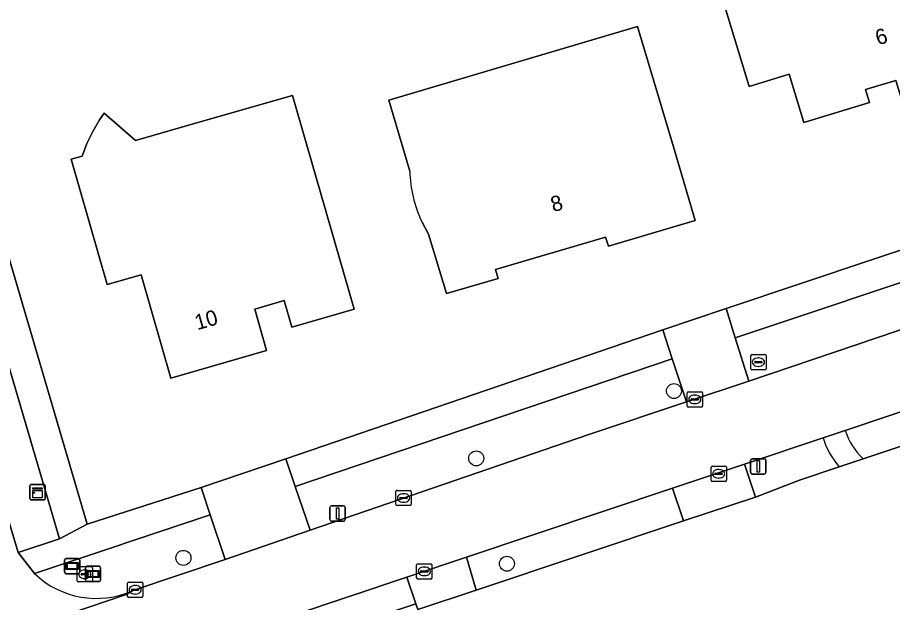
# Model space of a CAD drawing. Extents: x 162417 to 163722, y 384268 to 385417.
# Drawn here: x 163329 to 163386, y 384597 to 384635.2 of the extents above; entities that cross this region are included whole.
import ezdxf

# ---------------------------------------------------------------- set-up
doc = ezdxf.new("R2010")
doc.units = 0
for name, color, linetype in [('IMGEO_Berm_groen', 7, 'Continuous'), ('IMGEO_Boom', 7, 'Continuous'), ('IMGEO_Brandkraan', 7, 'Continuous'), ('IMGEO_Erf', 7, 'Continuous'), ('IMGEO_Groenvoorziening', 7, 'Continuous'), ('IMGEO_Kast', 7, 'Continuous'), ('IMGEO_Kolk', 7, 'Continuous'), ('IMGEO_Lichtmast', 7, 'Continuous'), ('IMGEO_Pand', 7, 'Continuous'), ('IMGEO_Pand_nummerreeks', 7, 'Continuous'), ('IMGEO_Rijbaan_lokaal_open', 7, 'Continuous'), ('IMGEO_Straatnaambord', 7, 'Continuous'), ('IMGEO_Verklikker', 7, 'Continuous'), ('IMGEO_Voetpad_open', 7, 'Continuous')]:
    doc.layers.add(name, color=color, linetype=linetype)

msp = doc.modelspace()

# ---------------------------------------------------------------- linework, layer by layer
at = {"layer": 'IMGEO_Berm_groen'}
for points in [[(163325.769, 384621.2), (163325.485, 384622.16), (163324.587, 384625.199), (163321.795, 384624.338), (163322.7, 384621.313), (163322.986, 384620.355), (163329.005, 384600.235), (163331.704, 384601.119)], [(163390.546, 384616.112), (163391.36, 384616.408), (163390.37, 384619.126), (163375.772, 384614.24), (163376.658, 384611.416)], [(163366.232, 384607.936), (163372.594, 384610.058), (163371.669, 384612.881), (163347.078, 384604.539), (163348.039, 384601.682)]]:
    msp.add_lwpolyline(points, close=True, dxfattribs=at)
for points in [[(163341.529, 384602.689), (163330.054, 384598.864)], [(163336.48, 384597.749), (163342.508, 384599.781), (163341.529, 384602.689)]]:
    msp.add_lwpolyline(points, dxfattribs=at)
msp.add_arc((163334.088, 384603.04), 5.807, 225.9892, 294.3236, dxfattribs=at)
at = {"layer": 'IMGEO_Boom'}
for centre in [(163371.785, 384610.77), (163358.881, 384606.376), (163339.782, 384599.881), (163360.886, 384599.501)]:
    msp.add_circle(centre, 0.489, dxfattribs=at)
at = {"layer": 'IMGEO_Brandkraan'}
for p, q in [((163376.793, 384612.228), (163376.793, 384613.08)), ((163376.868, 384613.154), (163377.72, 384613.154)), ((163377.794, 384613.08), (163377.794, 384612.228)), ((163377.052, 384612.648), (163377.052, 384612.66)), ((163377.49, 384612.611), (163377.092, 384612.611)), ((163377.095, 384612.697), (163377.493, 384612.697)), ((163377.281, 384612.934), (163377.306, 384612.934)), ((163377.536, 384612.66), (163377.536, 384612.648)), ((163377.72, 384612.154), (163376.868, 384612.154)), ((163377.304, 384612.374), (163377.279, 384612.374)), ((163332.846, 384598.385), (163332.846, 384599.237)), ((163332.921, 384599.311), (163333.773, 384599.311)), ((163333.105, 384598.805), (163333.105, 384598.817)), ((163333.543, 384598.768), (163333.145, 384598.768)), ((163333.148, 384598.854), (163333.546, 384598.854)), ((163333.334, 384599.091), (163333.359, 384599.091)), ((163333.589, 384598.817), (163333.589, 384598.805)), ((163333.847, 384599.237), (163333.847, 384598.385)), ((163333.773, 384598.311), (163332.921, 384598.311)), ((163333.357, 384598.531), (163333.332, 384598.531))]:
    msp.add_line(p, q, dxfattribs=at)
for points in [[(163376.793, 384612.228), (163376.793, 384613.08)], [(163376.868, 384613.154), (163377.72, 384613.154)], [(163377.794, 384613.08), (163377.794, 384612.228)], [(163377.72, 384612.154), (163376.868, 384612.154)], [(163332.846, 384598.385), (163332.846, 384599.237)], [(163332.921, 384599.311), (163333.773, 384599.311)], [(163333.847, 384599.237), (163333.847, 384598.385)], [(163333.773, 384598.311), (163332.921, 384598.311)]]:
    msp.add_lwpolyline(points, dxfattribs=at)
for centre, radius, start, end in [((163376.87, 384613.078), 0.0765, 91.552, 178.448), ((163376.87, 384613.078), 0.0765, 91.552, 178.448), ((163377.718, 384613.078), 0.0765, 1.552, 88.448), ((163377.718, 384613.078), 0.0765, 1.552, 88.448), ((163377.092, 384612.657), 0.0403, 85.8775, 175.7526), ((163377.089, 384612.647), 0.0366, 178.938, 274.7102), ((163377.493, 384612.654), 0.043, 264.8664, 352.4533), ((163377.497, 384612.659), 0.0386, 1.7309, 96.639), ((163376.87, 384612.23), 0.0765, 181.552, 268.448), ((163376.87, 384612.23), 0.0765, 181.552, 268.448), ((163377.718, 384612.23), 0.0765, 271.552, 358.448), ((163377.718, 384612.23), 0.0765, 271.552, 358.448), ((163332.923, 384599.235), 0.0765, 91.552, 178.448), ((163332.923, 384599.235), 0.0765, 91.552, 178.448), ((163333.145, 384598.814), 0.0403, 85.8775, 175.7526), ((163333.142, 384598.804), 0.0366, 178.938, 274.7102), ((163333.546, 384598.811), 0.043, 264.8664, 352.4533), ((163333.55, 384598.816), 0.0386, 1.7309, 96.639), ((163333.771, 384599.235), 0.0765, 1.552, 88.448), ((163333.771, 384599.235), 0.0765, 1.552, 88.448), ((163332.923, 384598.387), 0.0765, 181.552, 268.448), ((163332.923, 384598.387), 0.0765, 181.552, 268.448), ((163333.771, 384598.387), 0.0765, 271.552, 358.448), ((163333.771, 384598.387), 0.0765, 271.552, 358.448)]:
    msp.add_arc(centre, radius, start, end, dxfattribs=at)
for centre, major_axis, ratio, start_param, end_param in [((163377.28, 384612.654), (-0.387, 0.002), 0.722429, 4.712389, 7.853982), ((163377.305, 384612.654), (-0.39, 0.002), 0.717154, 1.570796, 4.712389), ((163333.333, 384598.811), (-0.387, 0.002), 0.722429, 4.712389, 7.853982), ((163333.358, 384598.811), (-0.39, 0.002), 0.717154, 1.570796, 4.712389)]:
    msp.add_ellipse(centre, major_axis=major_axis, ratio=ratio, start_param=start_param, end_param=end_param, dxfattribs=at)
at = {"layer": 'IMGEO_Erf'}
for points in [[(163310.09, 384681.76), (163333.508, 384602.071), (163340.928, 384604.472), (163346.471, 384606.34), (163371.048, 384614.758), (163375.186, 384616.159), (163389.679, 384621.017), (163394.532, 384622.596), (163398.708, 384624.299), (163402.801, 384626.194), (163403.314, 384626.415), (163406.716, 384627.995)], [(163354.543, 384625.127), (163353.186, 384629.758), (163369.415, 384634.561), (163371.747, 384626.703)], [(163371.747, 384626.703), (163373.169, 384621.909), (163367.504, 384620.235), (163367.319, 384620.817), (163360.137, 384618.695), (163360.316, 384618.12), (163356.948, 384617.133), (163355.771, 384621.007), (163355.324, 384621.829)], [(163419.582, 384621.874), (163409.408, 384616.22), (163410.03, 384614.861), (163400.639, 384612.147), (163394.917, 384609.966), (163384.126, 384606.347), (163382.571, 384605.826), (163379.98, 384604.957), (163377.103, 384603.845), (163372.405, 384602.287), (163358.873, 384597.777), (163355.069, 384596.509), (163354.943, 384596.875), (163344.075, 384593.215), (163344.183, 384592.925), (163342.307, 384592.282)]]:
    msp.add_lwpolyline(points, dxfattribs=at)
for points in [[(163392.516, 384640.667), (163393.965, 384635.882), (163391.345, 384635.089), (163393.445, 384628.155), (163387.663, 384626.41), (163386.518, 384630.192), (163386.261, 384631.043), (163384.28, 384630.444), (163384.538, 384629.593), (163380.261, 384628.298), (163379.31, 384631.443), (163376.692, 384630.651), (163375.243, 384635.437), (163374.953, 384636.394), (163377.573, 384637.187), (163376.623, 384640.332), (163382.891, 384642.229), (163381.746, 384646.012), (163380.405, 384650.271), (163388.837, 384652.823)], [(163350.916, 384616.107), (163346.854, 384614.936), (163346.352, 384616.675), (163344.429, 384616.12), (163345.208, 384613.419), (163338.963, 384611.616), (163337.021, 384618.356), (163334.807, 384617.718), (163332.449, 384625.902), (163333.165, 384626.108), (163333.478, 384626.928), (163333.86, 384627.718), (163334.308, 384628.472), (163334.611, 384628.896), (163336.658, 384627.116), (163341.022, 384628.374), (163346.891, 384630.066)]]:
    msp.add_lwpolyline(points, close=True, dxfattribs=at)
msp.add_arc((163362.771, 384625.334), 8.231, 181.4417, 205.2039, dxfattribs=at)
at = {"layer": 'IMGEO_Groenvoorziening'}
for points in [[(163384.126, 384606.347), (163394.917, 384609.966), (163395.176, 384610.568), (163394.546, 384612.095), (163382.96, 384608.203)], [(163381.515, 384607.717), (163376.389, 384605.995), (163377.103, 384603.845), (163379.98, 384604.957), (163382.571, 384605.826)]]:
    msp.add_lwpolyline(points, dxfattribs=at)
msp.add_lwpolyline([(163372.405, 384602.287), (163371.696, 384604.423), (163358.243, 384599.918), (163358.873, 384597.777)], close=True, dxfattribs=at)
for centre, radius, start, end in [((163387.063, 384609.486), 4.299, 197.3688, 226.908), ((163386.25, 384609.121), 4.939, 196.5137, 221.8473)]:
    msp.add_arc(centre, radius, start, end, dxfattribs=at)
at = {"layer": 'IMGEO_Kast'}
for p, q in [((163329.764, 384603.741), (163329.764, 384604.582)), ((163329.764, 384604.582), (163329.764, 384603.741)), ((163329.839, 384604.666), (163330.68, 384604.666)), ((163330.68, 384604.666), (163329.839, 384604.666)), ((163330.764, 384604.591), (163330.764, 384603.75)), ((163330.764, 384603.75), (163330.764, 384604.591)), ((163330.689, 384603.666), (163329.848, 384603.666)), ((163329.848, 384603.666), (163330.689, 384603.666))]:
    msp.add_line(p, q, dxfattribs=at)
for points in [[(163329.959, 384604.456), (163330.559, 384604.456), (163330.559, 384604.371), (163329.959, 384604.371), (163329.959, 384604.456)], [(163329.959, 384604.281), (163330.559, 384604.281), (163330.559, 384603.792), (163329.959, 384603.792), (163329.959, 384604.281)]]:
    msp.add_lwpolyline(points, dxfattribs=at)
msp.add_circle((163330.043, 384604.13), 0.0377, dxfattribs=at)
for centre, start, end in [((163329.842, 384604.588), 92.4484, 184.2845), ((163329.842, 384604.588), 92.4484, 184.2845), ((163330.686, 384604.588), 2.4484, 94.2845), ((163330.686, 384604.588), 2.4484, 94.2845), ((163329.842, 384603.744), 182.4484, 274.2845), ((163329.842, 384603.744), 182.4484, 274.2845), ((163330.686, 384603.744), 272.4484, 4.2845), ((163330.686, 384603.744), 272.4484, 4.2845)]:
    msp.add_arc(centre, 0.0779, start, end, dxfattribs=at)
at = {"layer": 'IMGEO_Kolk'}
for p, q in [((163372.644, 384609.799), (163372.644, 384610.651)), ((163372.719, 384610.725), (163373.571, 384610.725)), ((163372.903, 384610.219), (163372.903, 384610.231)), ((163373.341, 384610.182), (163372.943, 384610.182)), ((163372.946, 384610.268), (163373.344, 384610.268)), ((163373.132, 384610.505), (163373.157, 384610.505)), ((163373.387, 384610.231), (163373.387, 384610.219)), ((163373.645, 384610.651), (163373.645, 384609.799)), ((163373.571, 384609.725), (163372.719, 384609.725)), ((163373.155, 384609.945), (163373.13, 384609.945)), ((163374.2, 384604.941), (163374.2, 384605.793)), ((163374.275, 384605.867), (163375.127, 384605.867)), ((163374.688, 384605.647), (163374.713, 384605.647)), ((163375.201, 384605.793), (163375.201, 384604.941)), ((163374.459, 384605.361), (163374.459, 384605.373)), ((163374.897, 384605.324), (163374.499, 384605.324)), ((163374.502, 384605.41), (163374.9, 384605.41)), ((163374.711, 384605.087), (163374.686, 384605.087)), ((163374.943, 384605.373), (163374.943, 384605.361)), ((163375.127, 384604.867), (163374.275, 384604.867)), ((163353.641, 384603.362), (163353.641, 384604.214)), ((163353.716, 384604.288), (163354.568, 384604.288)), ((163354.129, 384604.068), (163354.154, 384604.068)), ((163354.642, 384604.214), (163354.642, 384603.362)), ((163353.9, 384603.782), (163353.9, 384603.794)), ((163354.338, 384603.745), (163353.94, 384603.745)), ((163353.943, 384603.831), (163354.341, 384603.831)), ((163354.152, 384603.508), (163354.127, 384603.508)), ((163354.384, 384603.794), (163354.384, 384603.782)), ((163354.568, 384603.288), (163353.716, 384603.288)), ((163354.996, 384598.574), (163354.996, 384599.426)), ((163355.071, 384599.5), (163355.923, 384599.5)), ((163355.997, 384599.426), (163355.997, 384598.574)), ((163355.255, 384598.994), (163355.255, 384599.006)), ((163355.693, 384598.957), (163355.295, 384598.957)), ((163355.298, 384599.043), (163355.696, 384599.043)), ((163355.484, 384599.28), (163355.509, 384599.28)), ((163355.739, 384599.006), (163355.739, 384598.994)), ((163336.131, 384597.372), (163336.131, 384598.224)), ((163336.206, 384598.298), (163337.058, 384598.298)), ((163337.132, 384598.224), (163337.132, 384597.372)), ((163355.923, 384598.5), (163355.071, 384598.5)), ((163355.507, 384598.72), (163355.482, 384598.72)), ((163336.39, 384597.792), (163336.39, 384597.804)), ((163336.828, 384597.755), (163336.43, 384597.755)), ((163336.433, 384597.841), (163336.831, 384597.841)), ((163336.619, 384598.078), (163336.644, 384598.078)), ((163336.874, 384597.804), (163336.874, 384597.792)), ((163337.058, 384597.298), (163336.206, 384597.298)), ((163336.642, 384597.518), (163336.617, 384597.518))]:
    msp.add_line(p, q, dxfattribs=at)
for points in [[(163372.644, 384609.799), (163372.644, 384610.651)], [(163372.719, 384610.725), (163373.571, 384610.725)], [(163373.645, 384610.651), (163373.645, 384609.799)], [(163373.571, 384609.725), (163372.719, 384609.725)], [(163374.2, 384604.941), (163374.2, 384605.793)], [(163374.275, 384605.867), (163375.127, 384605.867)], [(163375.201, 384605.793), (163375.201, 384604.941)], [(163375.127, 384604.867), (163374.275, 384604.867)], [(163353.641, 384603.362), (163353.641, 384604.214)], [(163353.716, 384604.288), (163354.568, 384604.288)], [(163354.642, 384604.214), (163354.642, 384603.362)], [(163354.568, 384603.288), (163353.716, 384603.288)], [(163354.996, 384598.574), (163354.996, 384599.426)], [(163355.071, 384599.5), (163355.923, 384599.5)], [(163355.997, 384599.426), (163355.997, 384598.574)], [(163336.131, 384597.372), (163336.131, 384598.224)], [(163336.206, 384598.298), (163337.058, 384598.298)], [(163337.132, 384598.224), (163337.132, 384597.372)], [(163355.923, 384598.5), (163355.071, 384598.5)], [(163337.058, 384597.298), (163336.206, 384597.298)]]:
    msp.add_lwpolyline(points, dxfattribs=at)
for centre, radius, start, end in [((163372.721, 384610.649), 0.0765, 91.552, 178.448), ((163372.721, 384610.649), 0.0765, 91.552, 178.448), ((163372.943, 384610.228), 0.0403, 85.8775, 175.7526), ((163372.94, 384610.218), 0.0366, 178.938, 274.7102), ((163373.344, 384610.225), 0.043, 264.8664, 352.4533), ((163373.348, 384610.23), 0.0386, 1.7309, 96.639), ((163373.569, 384610.649), 0.0765, 1.552, 88.448), ((163373.569, 384610.649), 0.0765, 1.552, 88.448), ((163372.721, 384609.801), 0.0765, 181.552, 268.448), ((163372.721, 384609.801), 0.0765, 181.552, 268.448), ((163373.569, 384609.801), 0.0765, 271.552, 358.448), ((163373.569, 384609.801), 0.0765, 271.552, 358.448), ((163374.277, 384605.791), 0.0765, 91.552, 178.448), ((163374.277, 384605.791), 0.0765, 91.552, 178.448), ((163375.125, 384605.791), 0.0765, 1.552, 88.448), ((163375.125, 384605.791), 0.0765, 1.552, 88.448), ((163374.499, 384605.37), 0.0403, 85.8775, 175.7526), ((163374.496, 384605.36), 0.0366, 178.938, 274.7102), ((163374.9, 384605.367), 0.043, 264.8664, 352.4533), ((163374.904, 384605.372), 0.0386, 1.7309, 96.639), ((163374.277, 384604.943), 0.0765, 181.552, 268.448), ((163374.277, 384604.943), 0.0765, 181.552, 268.448), ((163375.125, 384604.943), 0.0765, 271.552, 358.448), ((163375.125, 384604.943), 0.0765, 271.552, 358.448), ((163353.718, 384604.212), 0.0765, 91.552, 178.448), ((163353.718, 384604.212), 0.0765, 91.552, 178.448), ((163354.566, 384604.212), 0.0765, 1.552, 88.448), ((163354.566, 384604.212), 0.0765, 1.552, 88.448), ((163353.718, 384603.364), 0.0765, 181.552, 268.448), ((163353.718, 384603.364), 0.0765, 181.552, 268.448), ((163353.94, 384603.791), 0.0403, 85.8775, 175.7526), ((163353.937, 384603.781), 0.0366, 178.938, 274.7102), ((163354.341, 384603.788), 0.043, 264.8664, 352.4533), ((163354.345, 384603.793), 0.0386, 1.7309, 96.639), ((163354.566, 384603.364), 0.0765, 271.552, 358.448), ((163354.566, 384603.364), 0.0765, 271.552, 358.448), ((163355.073, 384599.424), 0.0765, 91.552, 178.448), ((163355.073, 384599.424), 0.0765, 91.552, 178.448), ((163355.921, 384599.424), 0.0765, 1.552, 88.448), ((163355.921, 384599.424), 0.0765, 1.552, 88.448), ((163355.295, 384599.003), 0.0403, 85.8775, 175.7526), ((163355.292, 384598.993), 0.0366, 178.938, 274.7102), ((163355.696, 384599), 0.043, 264.8664, 352.4533), ((163355.7, 384599.005), 0.0386, 1.7309, 96.639), ((163336.208, 384598.222), 0.0765, 91.552, 178.448), ((163336.208, 384598.222), 0.0765, 91.552, 178.448), ((163337.056, 384598.222), 0.0765, 1.552, 88.448), ((163337.056, 384598.222), 0.0765, 1.552, 88.448), ((163355.073, 384598.576), 0.0765, 181.552, 268.448), ((163355.073, 384598.576), 0.0765, 181.552, 268.448), ((163355.921, 384598.576), 0.0765, 271.552, 358.448), ((163355.921, 384598.576), 0.0765, 271.552, 358.448), ((163336.43, 384597.801), 0.0403, 85.8775, 175.7526), ((163336.427, 384597.791), 0.0366, 178.938, 274.7102), ((163336.831, 384597.798), 0.043, 264.8664, 352.4533), ((163336.835, 384597.803), 0.0386, 1.7309, 96.639), ((163336.208, 384597.374), 0.0765, 181.552, 268.448), ((163336.208, 384597.374), 0.0765, 181.552, 268.448), ((163337.056, 384597.374), 0.0765, 271.552, 358.448), ((163337.056, 384597.374), 0.0765, 271.552, 358.448)]:
    msp.add_arc(centre, radius, start, end, dxfattribs=at)
for centre, major_axis, ratio, start_param, end_param in [((163373.131, 384610.225), (-0.387, 0.002), 0.722429, 4.712389, 7.853982), ((163373.156, 384610.225), (-0.39, 0.002), 0.717154, 1.570796, 4.712389), ((163374.687, 384605.367), (-0.387, 0.002), 0.722429, 4.712389, 7.853982), ((163374.712, 384605.367), (-0.39, 0.002), 0.717154, 1.570796, 4.712389), ((163354.128, 384603.788), (-0.387, 0.002), 0.722429, 4.712389, 7.853982), ((163354.153, 384603.788), (-0.39, 0.002), 0.717154, 1.570796, 4.712389), ((163355.483, 384599), (-0.387, 0.002), 0.722429, 4.712389, 7.853982), ((163355.508, 384599), (-0.39, 0.002), 0.717154, 1.570796, 4.712389), ((163336.618, 384597.798), (-0.387, 0.002), 0.722429, 4.712389, 7.853982), ((163336.643, 384597.798), (-0.39, 0.002), 0.717154, 1.570796, 4.712389)]:
    msp.add_ellipse(centre, major_axis=major_axis, ratio=ratio, start_param=start_param, end_param=end_param, dxfattribs=at)
at = {"layer": 'IMGEO_Lichtmast'}
for p, q in [((163376.785, 384605.453), (163376.785, 384606.253)), ((163376.785, 384606.253), (163376.785, 384605.453)), ((163376.885, 384606.353), (163377.675, 384606.353)), ((163377.675, 384606.353), (163376.885, 384606.353)), ((163377.775, 384606.253), (163377.775, 384605.453)), ((163377.775, 384605.453), (163377.775, 384606.253)), ((163377.675, 384605.353), (163376.885, 384605.353)), ((163376.885, 384605.353), (163377.675, 384605.353)), ((163349.34, 384602.378), (163349.34, 384603.178)), ((163349.34, 384603.178), (163349.34, 384602.378)), ((163349.44, 384603.278), (163350.23, 384603.278)), ((163350.23, 384603.278), (163349.44, 384603.278)), ((163350.33, 384603.178), (163350.33, 384602.378)), ((163350.33, 384602.378), (163350.33, 384603.178)), ((163350.23, 384602.278), (163349.44, 384602.278)), ((163349.44, 384602.278), (163350.23, 384602.278))]:
    msp.add_line(p, q, dxfattribs=at)
for points in [[(163377.205, 384606.228), (163377.355, 384606.228), (163377.355, 384605.478), (163377.205, 384605.478), (163377.205, 384606.228)], [(163349.76, 384603.153), (163349.91, 384603.153), (163349.91, 384602.403), (163349.76, 384602.403), (163349.76, 384603.153)]]:
    msp.add_lwpolyline(points, dxfattribs=at)
for centre, start, end in [((163376.885, 384606.253), 90, 180), ((163376.885, 384606.253), 90, 180), ((163377.675, 384606.253), 0, 90), ((163377.675, 384606.253), 360, 90), ((163376.885, 384605.453), 180, 270), ((163376.885, 384605.453), 180, 270), ((163377.675, 384605.453), 270, 0), ((163377.675, 384605.453), 270, 0), ((163349.44, 384603.178), 90, 180), ((163349.44, 384603.178), 90, 180), ((163350.23, 384603.178), 0, 90), ((163350.23, 384603.178), 360, 90), ((163349.44, 384602.378), 180, 270), ((163349.44, 384602.378), 180, 270), ((163350.23, 384602.378), 270, 0), ((163350.23, 384602.378), 270, 0)]:
    msp.add_arc(centre, 0.1, start, end, dxfattribs=at)
at = {"layer": 'IMGEO_Pand'}
for points in [[(163375.243, 384635.437), (163376.692, 384630.651), (163379.31, 384631.443), (163380.261, 384628.298), (163384.538, 384629.593), (163384.28, 384630.444), (163386.261, 384631.043), (163386.518, 384630.192), (163387.663, 384626.41), (163393.445, 384628.155), (163391.345, 384635.089), (163393.965, 384635.882), (163392.516, 384640.667), (163388.837, 384652.823), (163380.405, 384650.271), (163381.746, 384646.012), (163382.891, 384642.229), (163376.623, 384640.332), (163377.573, 384637.187), (163374.953, 384636.394)], [(163346.891, 384630.066), (163341.022, 384628.374), (163336.658, 384627.116), (163334.611, 384628.896), (163334.308, 384628.472), (163333.86, 384627.718), (163333.478, 384626.928), (163333.165, 384626.108), (163332.449, 384625.902), (163334.807, 384617.718), (163337.021, 384618.356), (163338.963, 384611.616), (163345.208, 384613.419), (163344.429, 384616.12), (163346.352, 384616.675), (163346.854, 384614.936), (163350.916, 384616.107)]]:
    msp.add_lwpolyline(points, close=True, dxfattribs=at)
msp.add_lwpolyline([(163355.324, 384621.829), (163355.771, 384621.007), (163356.948, 384617.133), (163360.316, 384618.12), (163360.137, 384618.695), (163367.319, 384620.817), (163367.504, 384620.235), (163373.169, 384621.909), (163371.747, 384626.703), (163369.415, 384634.561), (163353.186, 384629.758), (163354.543, 384625.127)], dxfattribs=at)
msp.add_arc((163362.771, 384625.334), 8.231, 181.4417, 205.2039, dxfattribs=at)
at = {"layer": 'IMGEO_Rijbaan_lokaal_open'}
for points in [[(163330.054, 384598.864), (163329.005, 384600.235), (163322.986, 384620.355)], [(163390.546, 384616.112), (163376.658, 384611.416), (163372.594, 384610.058), (163366.232, 384607.936), (163348.039, 384601.682), (163342.508, 384599.781), (163336.48, 384597.749), (163336.053, 384597.486), (163319.165, 384591.77), (163318.779, 384591.691), (163301.239, 384585.814), (163296.688, 384584.289), (163280.347, 384578.814), (163278.037, 384578.038), (163277.613, 384577.896), (163273.724, 384576.587)], [(163317.177, 384586.045), (163324.882, 384588.717), (163325.068, 384588.78), (163335.735, 384592.381), (163354.346, 384598.613), (163358.243, 384599.918), (163371.696, 384604.423), (163376.389, 384605.995), (163381.515, 384607.717), (163382.96, 384608.203), (163394.546, 384612.095)], [(163318.779, 384591.691), (163319.165, 384591.77), (163336.053, 384597.486), (163336.48, 384597.749)]]:
    msp.add_lwpolyline(points, dxfattribs=at)
msp.add_arc((163334.088, 384603.04), 5.807, 225.9892, 294.3236, dxfattribs=at)
at = {"layer": 'IMGEO_Straatnaambord'}
for p, q in [((163332.026, 384598.948), (163332.026, 384599.748)), ((163332.026, 384599.748), (163332.026, 384598.948)), ((163332.126, 384599.848), (163332.916, 384599.848)), ((163332.916, 384599.848), (163332.126, 384599.848)), ((163333.016, 384599.748), (163333.016, 384598.948)), ((163333.016, 384598.948), (163333.016, 384599.748)), ((163332.916, 384598.848), (163332.126, 384598.848)), ((163332.126, 384598.848), (163332.916, 384598.848))]:
    msp.add_line(p, q, dxfattribs=at)
for points in [[(163332.127, 384599.58), (163332.915, 384599.58), (163332.915, 384599.116), (163332.127, 384599.116), (163332.127, 384599.58)], [(163332.192, 384599.515), (163332.192, 384599.181), (163332.85, 384599.181), (163332.85, 384599.515), (163332.192, 384599.515)]]:
    msp.add_lwpolyline(points, dxfattribs=at)
for centre, start, end in [((163332.126, 384599.748), 90, 180), ((163332.126, 384599.748), 90, 180), ((163332.916, 384599.748), 0, 90), ((163332.916, 384599.748), 360, 90), ((163332.126, 384598.948), 180, 270), ((163332.126, 384598.948), 180, 270), ((163332.916, 384598.948), 270, 0), ((163332.916, 384598.948), 270, 0)]:
    msp.add_arc(centre, 0.1, start, end, dxfattribs=at)
at = {"layer": 'IMGEO_Verklikker'}
for p, q in [((163333.487, 384599.33), (163334.277, 384599.33)), ((163334.277, 384599.33), (163333.487, 384599.33)), ((163333.387, 384598.43), (163333.387, 384599.23)), ((163333.387, 384599.23), (163333.387, 384598.43)), ((163334.377, 384599.23), (163334.377, 384598.43)), ((163334.377, 384598.43), (163334.377, 384599.23)), ((163334.277, 384598.33), (163333.487, 384598.33)), ((163333.487, 384598.33), (163334.277, 384598.33))]:
    msp.add_line(p, q, dxfattribs=at)
for points in [[(163333.488, 384599.062), (163334.276, 384599.062), (163334.276, 384598.598), (163333.488, 384598.598), (163333.488, 384599.062)], [(163333.553, 384598.997), (163333.553, 384598.663), (163334.211, 384598.663), (163334.211, 384598.997), (163333.553, 384598.997)]]:
    msp.add_lwpolyline(points, dxfattribs=at)
for centre, start, end in [((163333.487, 384599.23), 90, 180), ((163333.487, 384599.23), 90, 180), ((163334.277, 384599.23), 0, 90), ((163334.277, 384599.23), 360, 90), ((163333.487, 384598.43), 180, 270), ((163333.487, 384598.43), 180, 270), ((163334.277, 384598.43), 270, 0), ((163334.277, 384598.43), 270, 0)]:
    msp.add_arc(centre, 0.1, start, end, dxfattribs=at)
at = {"layer": 'IMGEO_Voetpad_open'}
for points in [[(163310.09, 384681.76), (163309.903, 384682.414), (163307.99, 384681.867), (163308.098, 384681.397), (163309.634, 384676.252), (163310.423, 384673.599), (163314.36, 384660.087), (163311.865, 384659.348), (163314.204, 384651.541), (163316.675, 384652.273), (163319.815, 384641.564), (163320.535, 384638.911), (163324.332, 384626.062), (163321.537, 384625.199), (163321.795, 384624.338), (163324.587, 384625.199), (163325.485, 384622.16), (163325.769, 384621.2), (163331.704, 384601.119), (163333.508, 384602.071)], [(163375.772, 384614.24), (163390.37, 384619.126), (163389.679, 384621.017), (163375.186, 384616.159)], [(163371.669, 384612.881), (163372.594, 384610.058), (163376.658, 384611.416), (163375.772, 384614.24), (163375.186, 384616.159), (163371.048, 384614.758)], [(163371.669, 384612.881), (163371.048, 384614.758), (163346.471, 384606.34), (163347.078, 384604.539)], [(163348.039, 384601.682), (163347.078, 384604.539), (163346.471, 384606.34), (163340.928, 384604.472), (163341.529, 384602.689), (163342.508, 384599.781)], [(163371.696, 384604.423), (163372.405, 384602.287), (163377.103, 384603.845), (163376.389, 384605.995)], [(163341.529, 384602.689), (163340.928, 384604.472), (163333.508, 384602.071), (163331.704, 384601.119), (163329.005, 384600.235), (163330.054, 384598.864)], [(163358.243, 384599.918), (163354.346, 384598.613), (163354.943, 384596.875), (163355.069, 384596.509), (163358.873, 384597.777)]]:
    msp.add_lwpolyline(points, close=True, dxfattribs=at)
for points in [[(163382.96, 384608.203), (163381.515, 384607.717)], [(163382.571, 384605.826), (163384.126, 384606.347)], [(163344.183, 384592.925), (163344.075, 384593.215), (163354.943, 384596.875), (163354.346, 384598.613), (163335.735, 384592.381)]]:
    msp.add_lwpolyline(points, dxfattribs=at)
for centre, radius, start, end in [((163387.063, 384609.486), 4.299, 197.3688, 226.908), ((163386.25, 384609.121), 4.939, 196.5137, 221.8473)]:
    msp.add_arc(centre, radius, start, end, dxfattribs=at)

# ---------------------------------------------------------------- texts
at = {"layer": 'IMGEO_Pand_nummerreeks'}
for s, rotation, p in [('6', 16.8239, (163385.097, 384633.324)), ('8', 16.4603, (163363.911, 384622.437)), ('10', 16.1058, (163340.682, 384614.735))]:
    msp.add_text(s, height=1, rotation=rotation, dxfattribs=at).set_placement(p)

doc.saveas('drawing.dxf')
